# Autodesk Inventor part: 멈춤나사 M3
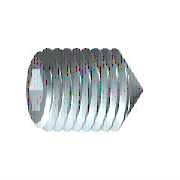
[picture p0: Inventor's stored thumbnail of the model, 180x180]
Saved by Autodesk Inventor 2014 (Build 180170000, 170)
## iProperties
IsCustomPart: 1
Created: 2012-02
Part Number: 멈춤나사 M3
Material: 강철, 연강
Description: 6각 소켓 머리 없는 멈춤 나사
Document SubType Name: Modeling
Standard: KS B 1028
Designer: test
Standards Organization: KS
Language: ko-KR
Size Designation: 원추점 M3x8
Categories: <MemberInstance><Categories><Category DisplayName="조임쇠" InternalName="e4da775c-781d-43d5-af7c-5136215cf5a6" Mnemonic="FSTN"><Category DisplayName="볼트" InternalN
Density: 1 g/cm^3
Appearance: Steel
Author: test
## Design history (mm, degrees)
sketch "스케치1"
  geometry: L1 (0, 0)-(5.5, 0); L2 (8, 0.866)-(8, 1.5); L3 (8, 1.5)-(0, 1.5); L4 (8, 0.866)-(6, 0.866); L5 (6, 0.866)-(5.5, 0); L6 (0, -0.3)-(0, 1.8) reference; L7 (0, 1.5)-(0, 0)
  constraints: 13 end point, 3 parallel, 1 collinear, 1 perpendicular, 1 point on line
  dimensions: "d0" = 2 distance of L2.start L4.end (= INTI); "d1" = 60 deg angle of L5 L1; "d2" = 3 diameter of L3 L1 (= NND); "d3" = 1.73205 diameter of L4 L1 (= 1.1547 x SW); "d5" = 8 distance from line of L2 L3.end (= NLG)
revolve "본체" sketch "스케치1" stored, may be unused: angle "d6" = 90 deg
sketch "스케치2"
  geometry: L1 (-0.433, 0.75)-(0.433, 0.75); L2 (0.433, 0.75)-(0.866, 0); L3 (0.866, 0)-(0.433, -0.75); L4 (0.433, -0.75)-(-0.433, -0.75); L5 (-0.433, -0.75)-(-0.866, 0); L6 (-0.866, 0)-(-0.433, 0.75); 3 further points
  constraints: 12 end point, 1 coincident, 1 horizontal, 13 other
extrude "슬롯" join sketch "스케치2" taper "d7" = 0 deg; stored distance "d21" = 10
workaxis "Work Axis1"
workplane "Work Plane1"
sketch "스케치4"
  geometry: L1 (0, 0.15)-(-1.35, 1.5) reference; L2 (0, -0.15)-(-1.35, -1.5) reference; L3 (-1.35, -1.5)-(0.15, 0); L4 (-1.35, 1.5)-(0.15, 0); 2 further points
  constraints: 4 end point, 1 coincident, 1 collinear, 1 horizontal alignment
body "Solid1"
feature "스레드" dims "d12" = 8 (= NLG), "d13" = 0
chamfer "모따기1" distance "d8" = 1.35 (computed from NND, SPD, FAWI); stored, may be unused: angle "d9" = 45 deg (= FAWI), second distance "d34" = 1.35 (computed from NND, SPD, FAWI)
chamfer "모따기2" distance "d10" = 0.30673 (= -0.5 x GD1 + 0.5 x NND); stored, may be unused: angle "d11" = 45 deg (= FAWI), second distance "d35" = 0.30673 (= -0.5 x GD1 + 0.5 x NND)
other parameters: "NND" = 3 [user parameter; used in 5 equation terms], "NLG" = 8 [user parameter; used in 2 equation terms], "INTI" = 2 [user parameter; used in 1 equation term], "FAWI" = 45 deg [user parameter; used in 4 equation terms], "SW" = 1.5 [user parameter; used in 2 equation terms], "GD1" = 2.38655 (= THREADDIA - 1.2269 x PTC) [user parameter; used in 2 equation terms], "d4" = 0, "FAWI1" = 45 deg [user parameter], "SPD" = 0.3 [user parameter; used in 2 equation terms], "d36" = 0, "d37" = 0, "GUL" = 0.30673 (= 0.61345 x PTC) [user parameter], "TOA" = 30 deg [user parameter], "THREADDIA" = 3 [user parameter; used in 1 equation term], "PTC" = 0.5 [user parameter; used in 4 equation terms], "GAL" = 0.30673 (= 0.61345 x PTC) [user parameter], "E0" = 1.7325 (= 1.155 x SW) [user parameter]
